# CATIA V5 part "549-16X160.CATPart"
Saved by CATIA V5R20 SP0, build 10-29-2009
Part number: 549-16X160
Definition: NONE
Nomenclature: 549-16X160
Source: Unknown
Description: 549-16X160
Bounding box of the stored display mesh (mm): x 0 to 160, y -9.5 to 9.5, z -9.5 to 9.5
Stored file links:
  C:\Users\Utente\Desktop\IO LAVORO\3D X SITO CF\X SITO\PLASTICA\549\549-16X160.CATPart
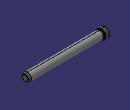
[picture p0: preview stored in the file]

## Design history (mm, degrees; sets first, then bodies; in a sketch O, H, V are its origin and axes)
Body1 "549-16X160" (main body)
  Solid1: solid without history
